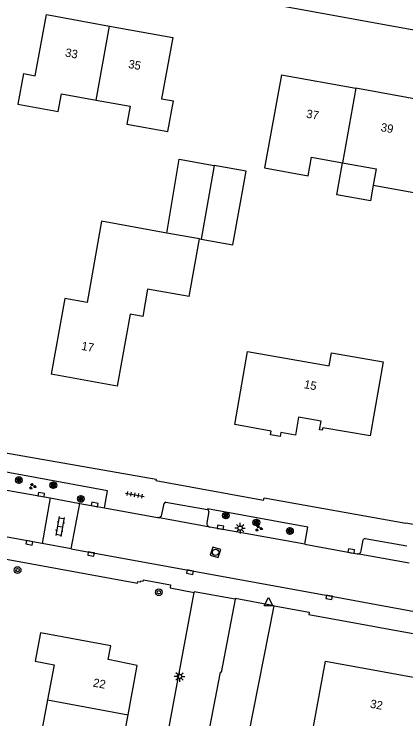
# Model space of a CAD drawing. Extents: x 132999 to 136000, y 398499 to 400501.
# Drawn here: x 133094.4 to 133141, y 399074 to 399157.9 of the extents above; entities that cross this region are included whole.
import ezdxf

# ---------------------------------------------------------------- set-up
doc = ezdxf.new("R2010")
doc.units = 0
for name, color, linetype in [('gg-afsc-muur', 7, 'Continuous'), ('gg-anno-huisnummerreeks BGT', 7, 'Continuous'), ('gg-bbg-gedigitaliseerde bebouwing', 7, 'Continuous'), ('gg-bbg-gedigitaliseerde bijgebouw', 7, 'Continuous'), ('gg-bbg-hoofdgebouw', 7, 'Continuous'), ('gg-bbg-luifel en loopbrug', 7, 'Continuous'), ('gg-bbg-tussenscheiding', 7, 'Continuous'), ('gg-knt-verharding', 7, 'Continuous'), ('gg-knt-verharding nz', 7, 'Continuous'), ('gt-grn-groengrens', 7, 'Continuous'), ('gt-symb-boom', 7, 'Continuous'), ('gt-symb-groenvak', 7, 'Continuous'), ('gt-symb-klinker verharding', 7, 'Continuous'), ('gt-symb-kolk', 7, 'Continuous'), ('gt-symb-lichtmast', 7, 'Continuous'), ('gt-symb-rioolschacht', 7, 'Continuous'), ('gt-symb-solitaire heester', 7, 'Continuous'), ('gt-symb-tegel verharding', 7, 'Continuous'), ('gt-symb-waterafsluiter', 7, 'Continuous')]:
    doc.layers.add(name, color=color, linetype=linetype)

# ---------------------------------------------------------------- blocks, each defined once
blk = doc.blocks.new('gt0-SH')
at = {"layer": 'gt-symb-solitaire heester'}
blk.add_circle((0, 0), 0.4, dxfattribs=at)
for centre, start, end in [((-0.346, 0.2), 270, 30), ((-0.346, -0.2), 330, 90), ((0, 0.4), 210, 330), ((0.346, 0.2), 150, 270), ((0.346, -0.2), 90, 210), ((0, -0.4), 30, 150)]:
    blk.add_arc(centre, 0.4, start, end, dxfattribs=at)
blk = doc.blocks.new('gt0-LMAST')
at = {"layer": 'gt-symb-lichtmast'}
for p, q in [((-0.182, 0.173), (-0.447, 0.438)), ((-0.005, 0.246), (-0.005, 0.621)), ((0.172, 0.173), (0.437, 0.438)), ((-0.255, -0.004), (-0.63, -0.004)), ((-0.182, -0.181), (-0.447, -0.446)), ((-0.005, -0.254), (-0.005, -0.629)), ((0.437, -0.446), (0.172, -0.181)), ((0.245, -0.004), (0.62, -0.004))]:
    blk.add_line(p, q, dxfattribs=at)
blk.add_circle((-0.005, -0.004), 0.25, dxfattribs=at)
blk = doc.blocks.new('gt0-GRVAK')
at = {"layer": 'gt-symb-groenvak'}
for p, q in [((-0.11, 0.189), (-0.228, 0.24)), ((-0.182, 0.153), (0.088, 0.153)), ((-0.091, 0.211), (-0.156, 0.322)), ((-0.047, 0.214), (-0.047, 0.393)), ((-0.004, 0.211), (0.061, 0.322)), ((0.015, 0.189), (0.133, 0.24)), ((0.262, -0.052), (0.197, 0.059)), ((0.305, -0.049), (0.305, 0.13)), ((0.349, -0.052), (0.414, 0.059)), ((-0.245, -0.228), (-0.363, -0.177)), ((-0.318, -0.264), (-0.047, -0.264)), ((-0.226, -0.206), (-0.291, -0.095)), ((-0.183, -0.203), (-0.183, -0.024)), ((-0.139, -0.206), (-0.074, -0.095)), ((-0.12, -0.228), (-0.002, -0.177)), ((0.243, -0.074), (0.125, -0.023)), ((0.17, -0.11), (0.441, -0.11)), ((0.368, -0.074), (0.486, -0.023))]:
    blk.add_line(p, q, dxfattribs=at)
blk = doc.blocks.new('gt0-KOLK')
at = {"layer": 'gt-symb-kolk'}
blk.add_lwpolyline([(0, 0), (0.375, 0), (0.375, 0.4), (-0.375, 0.4), (-0.375, 0), (0, 0)], dxfattribs=at)
blk = doc.blocks.new('gt0-TEG1')
at = {"layer": 'gt-symb-tegel verharding'}
for p, q in [((-1.125, 0), (1.125, 0)), ((-0.9, -0.25), (-0.9, 0.25)), ((-0.45, -0.25), (-0.45, 0.25)), ((0, -0.25), (0, 0.25)), ((0.45, -0.25), (0.45, 0.25)), ((0.9, -0.25), (0.9, 0.25))]:
    blk.add_line(p, q, dxfattribs=at)
blk = doc.blocks.new('gt0-KL1')
at = {"layer": 'gt-symb-klinker verharding'}
for p, q in [((-1.15, 0.3), (1.15, 0.3)), ((-1, -0.3), (-1, 0.3)), ((-0.5, 0.3), (-0.5, 0.45)), ((0, -0.3), (0, 0.3)), ((0.5, 0.3), (0.5, 0.45)), ((1, -0.3), (1, 0.3)), ((-1.15, -0.3), (1.15, -0.3)), ((-0.5, -0.45), (-0.5, -0.3)), ((0.5, -0.45), (0.5, -0.3))]:
    blk.add_line(p, q, dxfattribs=at)
blk = doc.blocks.new('gt0-RS')
at = {"layer": 'gt-symb-rioolschacht'}
blk.add_lwpolyline([(-0.5, -0.5), (0.5, -0.5), (0.5, 0.5), (-0.5, 0.5)], close=True, dxfattribs=at)
blk.add_circle((0, 0), 0.375, dxfattribs=at)
blk = doc.blocks.new('gt0-BOOM')
at = {"layer": 'gt-symb-boom'}
for radius in [0.4, 0.2]:
    blk.add_circle((0, 0), radius, dxfattribs=at)
blk = doc.blocks.new('gt0-WAFSL')
at = {"layer": 'gt-symb-waterafsluiter'}
for p, q in [((-0.5, -0.333), (0, 0.667)), ((0, 0.667), (0.5, -0.333)), ((0.5, -0.333), (-0.5, -0.333))]:
    blk.add_line(p, q, dxfattribs=at)

msp = doc.modelspace()

# ---------------------------------------------------------------- linework, layer by layer
at = {"layer": 'gg-afsc-muur'}
msp.add_line((133155.967, 399094.544), (133141.037, 399097.311), dxfattribs=at)
at = {"layer": 'gg-bbg-gedigitaliseerde bebouwing'}
for p, q in [((133137.157, 399137.516), (133141.977, 399136.636)), ((133115.257, 399124.269), (133116.485, 399131.124)), ((133116.485, 399131.124), (133116.683, 399131.089))]:
    msp.add_line(p, q, dxfattribs=at)
for points in [[(133095.55, 399150.8), (133094.886, 399147.154), (133099.69, 399146.279), (133100.076, 399148.399), (133104.198, 399147.649)], [(133126.251, 399150.67), (133124.226, 399139.576), (133129.43, 399138.626), (133129.838, 399140.86), (133133.523, 399140.188)], [(133104.198, 399147.649), (133108.25, 399146.911), (133107.866, 399144.8), (133112.735, 399143.914), (133113.4, 399147.55)], [(133133.523, 399140.188), (133137.512, 399139.46), (133137.157, 399137.516)], [(133112.628, 399131.827), (133104.859, 399133.221), (133103.128, 399123.575), (133100.472, 399124.051), (133098.85, 399115.01)], [(133120.69, 399109.02), (133122.207, 399117.728), (133131.935, 399116.034), (133132.204, 399117.577), (133138.349, 399116.506), (133136.811, 399107.68)], [(133096.97, 399080.85), (133099.196, 399080.435), (133098.417, 399076.256)], [(133098.417, 399076.256), (133097.627, 399072.016), (133095.44, 399072.423)]]:
    msp.add_lwpolyline(points, dxfattribs=at)
at = {"layer": 'gg-bbg-gedigitaliseerde bijgebouw'}
for points in [[(133112.628, 399131.827), (133114.075, 399140.64), (133118.231, 399139.878)], [(133116.683, 399131.089), (133120.463, 399130.411), (133122.039, 399139.195), (133118.231, 399139.878)]]:
    msp.add_lwpolyline(points, dxfattribs=at)
at = {"layer": 'gg-bbg-hoofdgebouw'}
msp.add_line((133126.251, 399150.67), (133135.107, 399149.062), dxfattribs=at)
for points in [[(133095.55, 399150.8), (133096.97, 399150.54), (133098.29, 399157.82), (133105.798, 399156.455)], [(133105.798, 399156.455), (133113.31, 399155.09), (133111.98, 399147.81), (133113.4, 399147.55)], [(133143.029, 399142.316), (133143.98, 399147.45), (133135.107, 399149.062)], [(133115.257, 399124.269), (133110.326, 399125.153), (133109.742, 399121.895), (133108.246, 399122.163), (133106.71, 399113.6), (133098.85, 399115.01)], [(133136.811, 399107.68), (133131.15, 399108.66), (133131.09, 399108.35), (133130.77, 399108.41), (133130.95, 399109.42), (133128.29, 399109.92), (133127.9, 399107.75), (133126.17, 399108.07), (133126.1, 399107.61), (133124.95, 399107.82), (133125.02, 399108.23), (133120.69, 399109.02)], [(133108, 399074.47), (133109.1, 399080.37), (133105.62, 399081.05), (133105.94, 399082.71), (133097.59, 399084.25), (133096.97, 399080.85)], [(133129.352, 399069.213), (133131.48, 399080.87), (133145.22, 399078.37), (133143.737, 399070.093), (133143.72, 399069.995)], [(133094.827, 399069.045), (133103.15, 399067.56), (133103.2, 399067.82), (133103.04, 399067.86), (133103.31, 399069.23), (133106.9, 399068.57), (133108, 399074.47)]]:
    msp.add_lwpolyline(points, dxfattribs=at)
at = {"layer": 'gg-bbg-luifel en loopbrug'}
msp.add_lwpolyline([(133137.157, 399137.516), (133136.818, 399135.661), (133132.829, 399136.389), (133133.523, 399140.188)], dxfattribs=at)
at = {"layer": 'gg-bbg-tussenscheiding'}
for p, q in [((133104.198, 399147.649), (133105.798, 399156.455)), ((133135.107, 399149.062), (133133.523, 399140.188)), ((133118.231, 399139.878), (133116.683, 399131.089)), ((133116.485, 399131.124), (133112.628, 399131.827)), ((133098.417, 399076.256), (133108, 399074.47))]:
    msp.add_line(p, q, dxfattribs=at)
at = {"layer": 'gg-knt-verharding'}
for p, q in [((133088.559, 399102.15), (133098.73, 399100.292)), ((133098.73, 399100.292), (133097.766, 399094.887)), ((133098.73, 399100.292), (133102.248, 399099.647)), ((133101.248, 399094.251), (133102.248, 399099.647)), ((133102.248, 399099.647), (133105.195, 399099.108)), ((133105.195, 399099.108), (133111.513, 399097.959)), ((133112.036, 399098.307), (133112.286, 399099.647)), ((133112.509, 399099.807), (133117.451, 399098.908)), ((133117.601, 399098.691), (133117.362, 399097.342)), ((133129.016, 399094.778), (133117.732, 399096.829)), ((133101.248, 399094.251), (133097.766, 399094.887)), ((133135.741, 399093.997), (133135.98, 399095.321)), ((133136.203, 399095.467), (133141.141, 399094.6)), ((133129.016, 399094.778), (133135.256, 399093.641)), ((133105.892, 399035.089), (133115.855, 399089.049))]:
    msp.add_line(p, q, dxfattribs=at)
for points in [[(133187.008, 399146.493), (133186.762, 399146.936), (133185.994, 399147.608), (133185.074, 399148.035), (133184.1, 399148.308), (133139.809, 399156.359), (133056.989, 399171.443), (133057.003, 399171.522), (133036.364, 399175.27)], [(133025.21, 399118.235), (133052.764, 399113.302), (133052.665, 399112.75), (133071.5, 399109.332), (133071.53, 399109.48), (133075.47, 399108.789), (133075.54, 399109.183), (133081.222, 399108.094), (133081.171, 399107.798), (133111.331, 399102.534), (133111.305, 399102.387), (133124.115, 399100.017), (133124.188, 399100.326), (133141.037, 399097.311)], [(133097.766, 399094.887), (133039.372, 399105.467), (133024.137, 399108.202), (133019.986, 399108.969)], [(133105.195, 399099.108), (133105.568, 399101.16), (133088.299, 399104.313), (133088.286, 399104.244)], [(133064.367, 399098.472), (133077.946, 399096.036), (133077.939, 399095.999), (133078.532, 399095.891), (133078.507, 399095.752), (133085.447, 399094.497), (133085.469, 399094.618), (133090.482, 399093.687), (133090.457, 399093.552), (133109.139, 399090.162), (133109.181, 399090.35), (133109.475, 399090.295), (133109.503, 399090.443), (133109.798, 399090.388), (133109.825, 399090.535), (133113.029, 399089.94), (133112.991, 399089.583), (133115.855, 399089.049)], [(133129.016, 399094.778), (133129.388, 399096.822), (133117.464, 399098.981), (133117.451, 399098.908)], [(133101.248, 399094.251), (133131.96, 399088.654), (133146.149, 399086.041), (133153.733, 399084.679), (133155.809, 399084.619), (133157.795, 399084.602)], [(133120.733, 399088.258), (133115.871, 399089.139), (133115.855, 399089.049)], [(133120.733, 399088.258), (133119.09, 399079.53), (133118.954, 399079.556), (133117.706, 399072.966), (133115.839, 399062.827), (133115.966, 399062.804), (133115.575, 399060.585)], [(133125.396, 399087.463), (133120.743, 399088.312), (133120.733, 399088.258)], [(133125.396, 399087.463), (133129.541, 399086.708), (133129.514, 399086.431), (133153.227, 399082.115)]]:
    msp.add_lwpolyline(points, dxfattribs=at)
for centre, radius, start, end in [((133112.478, 399099.614), 0.195, 80.92407, 170.39396), ((133111.571, 399098.439), 0.483, 263.12128, 344.15767), ((133117.398, 399098.711), 0.204, 354.4756, 74.83229), ((133117.833, 399097.292), 0.474, 173.89944, 257.70243), ((133136.174, 399095.268), 0.201, 81.72721, 164.69901), ((133135.302, 399094.086), 0.448, 264.07222, 348.48666)]:
    msp.add_arc(centre, radius, start, end, dxfattribs=at)
at = {"layer": 'gg-knt-verharding nz'}
for p, q in [((133117.732, 399096.829), (133111.513, 399097.959)), ((133141.434, 399092.516), (133135.256, 399093.641))]:
    msp.add_line(p, q, dxfattribs=at)
at = {"layer": 'gt-grn-groengrens'}
msp.add_line((133120.553, 399063.004), (133125.396, 399087.463), dxfattribs=at)

# ---------------------------------------------------------------- block references
at = {"layer": 'gt-symb-boom'}
for p in [(133094.859, 399091.715), (133111.663, 399089.07)]:
    msp.add_blockref('gt0-BOOM', p, dxfattribs=at)
at = {"layer": 'gt-symb-groenvak'}
for p in [(133096.634, 399101.674), (133123.53, 399096.674)]:
    msp.add_blockref('gt0-GRVAK', p, dxfattribs=at)
at = {"layer": 'gt-symb-klinker verharding', "rotation": -100.25359802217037}
msp.add_blockref('gt0-KL1', (133099.906, 399096.903), dxfattribs=at)
at = {"layer": 'gt-symb-kolk'}
for p, rotation in [((133097.639, 399100.492), -10.34454247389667), ((133103.999, 399099.326), -10.385682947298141), ((133118.956, 399096.611), -10.115025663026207), ((133096.299, 399095.155), 169.64606927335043), ((133134.508, 399093.777), -10.32866527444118), ((133103.641, 399093.814), 169.63813061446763), ((133115.399, 399091.664), 169.704536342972), ((133131.96, 399088.654), 169.56523953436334)]:
    msp.add_blockref('gt0-KOLK', p, dxfattribs=dict(at, rotation=rotation))
at = {"layer": 'gt-symb-lichtmast'}
for p in [(133121.328, 399096.707), (133114.124, 399079.051)]:
    msp.add_blockref('gt0-LMAST', p, dxfattribs=at)
at = {"layer": 'gt-symb-rioolschacht', "rotation": 162.55017196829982}
msp.add_blockref('gt0-RS', (133118.402, 399093.831), dxfattribs=at)
at = {"layer": 'gt-symb-solitaire heester'}
for p in [(133095.005, 399102.427), (133099.112, 399101.814), (133102.387, 399100.176), (133119.63, 399098.214), (133123.259, 399097.367), (133127.255, 399096.363)]:
    msp.add_blockref('gt0-SH', p, dxfattribs=at)
at = {"layer": 'gt-symb-tegel verharding', "rotation": -10.140793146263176}
msp.add_blockref('gt0-TEG1', (133108.805, 399100.656), dxfattribs=at)
at = {"layer": 'gt-symb-waterafsluiter'}
msp.add_blockref('gt0-WAFSL', (133124.707, 399087.789), dxfattribs=at)

# ---------------------------------------------------------------- texts
at = {"layer": 'gg-anno-huisnummerreeks BGT'}
for s, rotation, p in [('33', 349.7, (133100.457, 399152.852)), ('35', 349.7, (133107.967, 399151.487)), ('37', 349.7, (133129.133, 399145.573)), ('39', 349.7, (133137.993, 399143.964)), ('17', 349.8, (133102.395, 399117.931)), ('15', 349.3, (133128.867, 399113.374)), ('22', 349.5, (133103.771, 399077.854)), ('32', 349.7, (133136.731, 399075.341))]:
    msp.add_text(s, height=1, rotation=rotation, dxfattribs=at).set_placement(p)

doc.saveas('drawing.dxf')
